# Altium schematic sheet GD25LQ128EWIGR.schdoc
size 127 x 101 mm
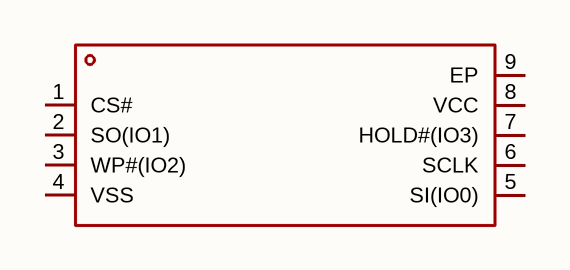
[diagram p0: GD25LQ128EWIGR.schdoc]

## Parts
U?  gd25lq128ewigr  [WSON-8_L6.0-W5.0-P1.27-BL-EP]  (value not drawn)

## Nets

Not connected (* = marked no-connect by the designer): U? 1(CS#) 2(SO(IO1)) 3(WP#(IO2)) 4(VSS) 5(SI(IO0)) 6(SCLK) 7(HOLD#(IO3)) 8(VCC) 9(EP)

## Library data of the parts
U? = gd25lq128ewigr: 接口类型:SPI;存储容量:128Mbit;时钟频率(fc):120MHz;; Manufacturer: GigaDevice(兆易创新); AddInBom: yes; ModelId: 72347fabc1e24788a361efd6527ab939; ModelName: WSON-8_L6.0-W5.0-H0.7-P1.27; ModelTransform: 237.007,196.85,0,90,0,0,0,0,0; Interface: SPI; Clock Frequency: 120MHz; Voltage - Supply: 1.65V~2V; Standby Supply Current: 35uA; Program / Erase Cycles: 100000次; Page Programming Time (Tpp): 500us; Block Erase Time(tBE): 160ms@(32KB); Data Retention - TDR (Year): 20年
